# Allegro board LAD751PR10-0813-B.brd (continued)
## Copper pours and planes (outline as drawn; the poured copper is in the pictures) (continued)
P1 on IN1 (solid shape): 69.35,39.47 69.35,34.7 69.03,34.39 67.76,34.39 67.45,34.7 67.45,39.4 67.83,39.78 69.03,39.78
P1 on IN3 (solid shape): 69.6,39.59 69.6,34.64 69.22,34.26 67.95,34.26 67.57,34.64 67.57,39.53 67.83,39.78 69.41,39.78
P1 on IN4 (solid shape): 69.73,39.59 69.73,34.58 69.54,34.39 67.76,34.39 67.45,34.7 67.45,39.44 67.47,39.5 67.48,39.57 67.89,39.97 69.35,39.97
P2 on TOP (solid shape): outline of 89 points within 58.62,34.39 65.67,41.88
P2 on BOTTOM (solid shape): 64.14,42.13 64.14,40.25 66.07,38.32 66.07,34.11 65.83,33.87 61.56,33.87 61.51,33.81 61.16,33.81 60.97,34 60.97,38.01 60.35,38.62 59.13,38.62 59.13,41.94 58.36,41.94 58.36,38.62 57.03,38.62 56.78,38.87 56.78,43.09 57.1,43.4 62.87,43.4
P2 on IN1 (solid shape): 63.76,41.12 63.76,39.53 63.51,39.28 60.84,39.28 60.52,39.59 60.52,41.05 60.84,41.37 63.51,41.37
P2 on IN3 (solid shape): 63.89,41.12 63.89,39.59 63.64,39.34 60.71,39.34 60.52,39.53 60.52,41.24 60.65,41.37 63.64,41.37
P2 on IN4 (solid shape): 63.89,41.12 63.89,39.34 63.64,39.08 60.78,39.08 60.52,39.34 60.52,41.12 60.84,41.43 63.57,41.43
POK on BOTTOM (solid shape): 227.73,37.41 227.73,36.32 227.24,35.83 223.4,35.83 223.17,36.06 223.17,37.5 223.35,37.67 227.46,37.67
PQ703_S on TOP (solid shape): 82.24,32.04 82.24,29.12 82.05,28.92 80.91,28.92 80.65,29.18 78.62,29.18 78.56,29.24 78.56,29.69 78.3,29.94 77.22,29.94 76.72,30.45 76.72,32.1 77.16,32.54 81.73,32.54
PQ703_S on BOTTOM (solid shape): outline of 133 points within 72.34,21.56 80.97,32.16
PSID-1 on TOP (solid shape): 318.21,50.83 318.21,50.32 317.83,49.94 317.83,48.93 317.89,48.86 318.52,48.86 318.65,48.74 318.65,47.53 318.52,47.4 317.89,47.4 317.51,47.78 317.51,48.23 316.94,48.8 316.94,50.71 317.25,51.02 318.02,51.02
PSID-2 on TOP (solid shape): 316.56,51.47 316.56,49.75 315.1,48.29 313.83,48.29 313.57,48.55 313.57,48.99 314.46,49.88 314.46,50.77 314.65,50.96 315.48,50.96 315.67,51.15 315.67,51.47 315.92,51.72 316.3,51.72
PSID-3 on TOP (solid shape): 315.16,47.21 315.16,46.64 314.91,46.39 312.3,46.39 312.17,46.51 312.17,46.96 312.3,47.09 313.19,47.09 313.57,47.47 314.91,47.47
PWR_R# on TOP (solid shape): 211.15,170.21 211.15,168.5 211.01,168.36 210.66,168.36 210.48,168.54 210.48,169.98 209.87,170.59 209.87,170.9 210,171.03 210.33,171.03
PWR_VGA_CORE_BOOT2 on BOTTOM (solid shape): 246.98,36.22 246.98,35.21 246.9,35.13 246.9,35.09 245.79,33.98 245.48,33.98 245.41,34.05 245.41,34.82 245.48,34.89 245.53,34.92 245.6,34.92 245.69,34.83 245.82,34.83 245.83,34.82 246.26,34.92 246.26,35.37 246.25,35.38 246.25,35.41 246.07,35.58 246.01,35.58 246,35.6 246,35.75 245.97,35.79 245.97,36.25 246,36.29 246.91,36.29
PWR_VGA_CORE_BOOT2_1 on BOTTOM (solid shape): 248.22,37.71 248.22,37.04 248.15,36.96 246.02,36.96 245.95,37.03 245.95,37.61 246.14,37.8 248.13,37.8
PWR_VGA_CORE_PHASE1 on BOTTOM (solid shape): 264.49,34.13 264.49,25.94 264.36,25.81 263.19,25.81 262.67,26.33 262.07,26.33 262.01,26.39 262.01,30.96 261.19,31.78 260.55,31.78 260.33,32 260.33,34.42 260.49,34.58 264.04,34.58
PWR_VGA_CORE_PHASE2 on TOP (solid shape): 253.56,34.13 253.56,32.16 253.5,32.1 250.9,32.1 250.77,32.23 250.77,34.07 250.96,34.26 253.44,34.26
PWR_VGA_CORE_PHASE2 on BOTTOM (solid shape): 248.12,36.23 248.12,35.62 247.53,35.03 247.53,34.19 247.28,33.94 247.01,33.94 246.67,33.61 245.88,33.61 245.82,33.67 245.82,33.79 245.87,33.83 245.87,33.83 247.19,35.15 247.19,36.26 247.22,36.28 248.07,36.28
PWR_VGA_CORE_PHASE2 on BOTTOM (solid shape): 256.49,34.32 256.49,32.16 255.47,31.15 255.47,26.45 255.22,26.19 253.18,26.19 252.87,26.51 252.87,30.58 251.48,31.96 251.48,31.97 251.41,32.07 251.32,32.13 251.31,32.14 250.64,32.8 250.64,34.26 251.02,34.64 256.17,34.64
RING2 on TOP (solid shape): 28.92,22.23 28.92,20.86 29.05,20.73 29.54,20.73 29.68,20.59 29.68,19.99 29.54,19.84 28.25,19.84 28.18,19.91 28.18,21.41 28.18,21.43 28.01,21.6 28.01,22.26 28.07,22.31 28.84,22.31
RING2 on BOTTOM (solid shape): 26.65,31.34 26.73,31.3 26.75,31.21 26.74,31.07 26.78,30.94 26.79,30.92 27.02,30.76 27.29,30.81 27.5,30.81 27.69,30.75 27.89,30.81 29.06,30.81 29.12,30.75 29.12,30.65 29.04,30.56 27.26,30.56 27.25,30.55 27.13,30.55 27.08,30.5 26.32,30.5 26.24,30.58 26.07,30.58 25.91,30.75 25.91,31.33 25.92,31.34
RING2 on IN1 (solid shape): 28.33,21.11 28.33,20.93 28.52,20.73 29.28,20.73 29.41,20.61 29.41,20.03 29.22,19.84 27.63,19.84 27.31,20.16 27.31,21.3 28.14,21.3
RING2 on IN1 (solid shape): 26.85,30.84 26.85,30.24 26.58,29.98 24.59,29.98 24.4,30.16 24.4,31.3 24.55,31.45 24.62,31.45 24.67,31.46 26.22,31.46
RING2_R on TOP (solid shape): 28.06,21.36 28.06,19.42 28.33,19.15 28.33,17.56 28.01,17.24 27.31,17.24 27.16,17.4 27.16,17.74 27.16,17.81 27.16,17.88 27.16,18.67 26.9,18.92 26.9,21.2 27.11,21.41 28.01,21.41
RING2_R on TOP (solid shape): 22.16,19.98 22.16,19.39 21.38,18.62 20.02,18.62 19.48,18.08 18.78,18.08 18.6,18.26 18.6,18.28 18.23,18.65 17.47,18.65 17.24,18.88 17.24,19.7 17.43,19.89 18.61,19.89 19.14,19.37 19.41,19.37 19.73,19.68 20.74,19.68 21.14,20.09 22.06,20.09
RING2_R on BOTTOM (solid shape): 29.02,18.08 29.02,17.47 28.96,17.42 28.25,17.42 28.08,17.24 27.31,17.24 27.12,17.43 27.12,17.62 27.25,17.75 27.5,17.75 27.89,18.13 28.96,18.13
RING2_R on IN1 (solid shape): 17.87,19.83 17.87,18.65 17.29,18.08 16.47,18.08 16.35,18.19 16.35,19.63 16.62,19.89 17.8,19.89
RING2_R on IN1 (solid shape): 22.17,21.09 22.17,19.79 21.93,19.55 21.14,19.55 20.95,19.74 20.95,20.9 21.22,21.16 22.09,21.16
RING2_R on IN1 (solid shape): 28.28,18.6 28.28,17.61 27.89,17.22 27.36,17.22 27.14,17.44 27.14,17.68 27.13,17.96 26.93,18.15 26.91,18.17 26.91,18.5 27.52,19.11 27.77,19.11
RJ45_CT on TOP (solid shape): 263.5,165.37 263.5,164.64 263.27,164.42 248.15,164.42 247.82,164.75 247.82,165.47 247.94,165.59 263.28,165.59
RJ45_CT on BOTTOM (solid shape): 264.19,165.36 264.19,162.46 264.17,162.44 261.86,162.44 261.82,162.47 261.82,165.55 262.01,165.73 263.82,165.73
SLEEVE on BOTTOM (solid shape): 29.64,21.87 29.64,20.9 29.28,20.54 28.14,20.54 27.12,19.53 26.74,19.53 26.45,19.23 26.45,18.39 26.41,18.36 25.99,18.36 25.9,18.44 25.9,19.25 26.04,19.4 26.04,19.97 26.17,20.1 26.68,20.1 27.06,20.48 27.06,21.09 27.37,21.39 28.24,21.39 28.96,22.11 29.4,22.11
SLEEVE on IN1 (solid shape): 29.05,31.56 29.05,30.21 28.92,30.07 27.17,30.07 26.99,30.25 26.99,30.88 26.85,31.02 26.85,31.58 26.99,31.72 28.89,31.72
SLEEVE on IN1 (solid shape): 31.41,22.25 31.41,21.53 31.12,21.24 31.12,21.24 30.87,21.34 30.62,21.24 30.48,21.24 30.24,21.34 30,21.25 29.98,21.24 29.92,21.24 29.57,20.89 29.06,20.89 28.84,21.11 28.84,22.29 29.03,22.48 31.18,22.48
SLEEVE_R on TOP (solid shape): 21.18,18.17 21.18,16.61 20.28,15.7 19.72,15.7 19.12,16.3 17.61,16.3 17.45,16.47 17.45,17.57 17.5,17.62 18.14,17.62 18.35,17.53 18.55,17.62 19.36,17.62 20.07,18.33 21.01,18.33
SLEEVE_R on BOTTOM (solid shape): 31.32,21.05 31.32,20.59 30.26,19.54 30.25,19.54 30.1,19.39 29.32,19.39 29.02,19.08 27.57,19.08 27.31,18.83 27.31,18.51 27.19,18.38 26.68,18.38 26.66,18.41 26.66,19.19 26.74,19.27 27.06,19.27 27.65,19.87 28.26,19.87 28.27,19.86 28.46,19.81 28.64,19.87 28.89,19.87 29.18,19.82 29.41,20 29.41,20.01 29.48,20.08 29.48,20.43 29.92,20.86 29.92,21.11 30.04,21.24 31.12,21.24
SLEEVE_R on IN3 (solid shape): 17.95,17.24 17.95,16.1 17.6,15.74 16.63,15.74 16.54,15.83 16.54,17.02 16.82,17.3 17.89,17.3
SLEEVE_R on IN3 (solid shape): 21.04,18.98 21.04,17.86 20.93,17.75 20.1,17.75 19.87,17.98 19.87,19.16 19.9,19.18 20.84,19.18
SLEEVE_R on IN3 (solid shape): 31.33,21.02 31.33,20.31 30.49,19.46 30.48,19.46 29.72,18.7 28.71,18.7 28.71,19.59 28.84,19.72 29.08,19.72 29.17,19.81 29.19,19.82 29.34,19.91 29.44,20.07 29.44,20.08 29.65,20.29 29.65,21.09 29.84,21.28 31.07,21.28
SNB_1.0VS_VGAP on BOTTOM (solid shape): 248.19,45.56 248.19,44.74 248.26,44.67 248.95,44.67 249.02,44.61 249.02,43.78 248.95,43.72 248.26,43.72 247.75,44.23 247.75,44.6 247.75,44.72 247.49,44.97 247.49,45.63 247.56,45.69 248.07,45.69
SNUB_CHG on TOP (solid shape): 64.02,21.24 64.02,20.73 64.27,20.48 65.22,20.48 65.35,20.35 65.35,18.96 65.16,18.76 64.27,18.76 63.45,19.59 63.45,21.3 63.51,21.37 63.89,21.37
SPK_L+_CONN on TOP (solid shape): 30.67,17.12 30.67,16.8 30.61,16.74 30.34,16.74 30.21,16.61 30.21,16.08 30.12,16 29.54,16 29.47,16.06 29.47,16.54 29.47,16.54 29.47,16.98 29.59,17.11 29.59,17.12 29.66,17.18 30.61,17.18
SPK_L+_CONN on TOP (solid shape): 48.71,12.99 48.71,12.41 48.59,12.29 48.18,12.29 47.94,12.05 47.59,12.05 47.5,12.04 47.41,12.01 44.54,12.01 44.33,12.22 44.33,13.05 44.54,13.25 48.44,13.25
SPK_L+_CONN on BOTTOM (solid shape): 48.83,14.89 48.83,13.06 48.78,13.02 48.78,12.42 48.31,11.95 47.88,11.95 47.57,12.26 47.57,12.8 48.01,13.24 48.01,14.88 48.25,15.11 48.6,15.11
SPK_L+_CONN on BOTTOM (solid shape): 36.07,5.46 36.16,5.46 36.67,4.95 36.67,4.62 36.58,4.54 36.29,4.54 36.22,4.47 36.22,2.86 36.19,2.83 35.6,2.83 35.53,2.89 35.53,5.11 35.89,5.46 36.07,5.46
SPK_L+_CONN on IN1 (solid shape): 45.67,13.05 45.67,12.41 45.41,12.16 43.82,12.16 43.63,11.97 43.38,11.97 43.06,12.29 43.06,12.8 43.57,13.3 45.41,13.3
SPK_L+_CONN on IN1 (solid shape): 36.73,6.09 36.73,6.06 36.71,6.04 36.69,6.02 36.71,6 36.71,5.68 36.65,5.62 36.54,5.62 36.41,5.49 36.41,5.24 36.59,5.06 36.65,4.99 36.71,4.94 36.71,4.53 36.66,4.47 35.81,4.47 35.42,4.86 35.42,6.21 35.81,6.59 36.23,6.59
SPK_L+_CONN on IN3 (solid shape): 30.81,17.07 30.81,16.6 31.06,16.35 31.06,15.59 30.81,15.34 30.11,15.34 29.57,15.88 29.57,17.11 29.77,17.32 30.55,17.32
SPK_L+_CONN on IN3 (solid shape): 37.28,6.7 37.28,6.06 37.03,5.81 36.71,5.81 36.46,5.56 36.46,5.11 36.71,4.86 36.71,4.6 36.52,4.41 35.63,4.41 35.44,4.6 35.44,6.06 36.27,6.89 37.09,6.89
SPK_L-_CONN on TOP (solid shape): 32.93,17.06 32.93,16.88 32.77,16.72 32.77,16.05 32.73,16.01 32.1,16.01 32.06,16.05 32.06,16.75 31.93,16.88 31.93,17.07 32.08,17.22 32.77,17.22
SPK_L-_CONN on TOP (solid shape): 46.24,11.1 47.28,11.1 47.48,10.9 48.57,10.9 48.75,10.73 48.75,10.02 48.62,9.89 46.03,9.89 45.28,10.64 45.28,11.53 45.41,11.65 45.68,11.65
SPK_L-_CONN on BOTTOM (solid shape): 39.75,3.98 39.75,3.14 39.56,2.95 39.19,2.95 39.06,3.08 37.45,3.08 37.4,3.13 37.4,4.02 37.48,4.1 38.42,4.1 38.42,4.1 39.63,4.1
SPK_L-_CONN on BOTTOM (solid shape): 50.08,14.91 50.08,10.81 49.19,9.92 47.65,9.92 47.51,10.07 47.51,10.93 47.63,11.06 48.7,11.06 49.13,11.48 49.13,13.05 49.28,13.21 49.28,14.93 49.47,15.12 49.87,15.12
SPK_L-_CONN on IN1 (solid shape): 39.58,5.36 39.58,3.2 39.32,2.95 39.07,2.95 39,3.02 39,3.33 38.37,3.96 38.37,5.05 38.74,5.42 39.51,5.42
SPK_L-_CONN on IN1 (solid shape): 45.87,11.53 45.87,10.4 45.72,10.25 43.64,10.25 43.51,10.38 43.51,11.08 44.05,11.62 45.78,11.62
SPK_L-_CONN on IN3 (solid shape): 32.96,17.12 32.96,15.28 32.77,15.09 32.07,15.09 31.88,15.28 31.88,16.54 31.95,16.61 31.95,17.12 32.08,17.25 32.83,17.25
SPK_L-_CONN on IN3 (solid shape): 39.59,4.59 39.59,3.06 39.44,2.92 38.97,2.92 38.24,3.65 38.24,4.79 38.36,4.92 39.25,4.92
SPK_R+_CONN on TOP (solid shape): 27.5,11.6 27.94,11.6 28.07,11.47 28.07,10.96 28.01,10.9 26.87,10.9 26.74,11.03 26.74,11.91 26.81,11.97 27.12,11.97
SPK_R+_CONN on TOP (solid shape): 48.75,9.06 48.75,8.34 48.61,8.21 47.51,8.21 47.28,7.98 45.69,7.98 45.19,7.48 44.75,7.48 44.34,7.89 44.34,8.15 45.38,9.19 48.62,9.19
SPK_R+_CONN on TOP (solid shape): 30.55,4.79 30.55,3.21 30.23,2.89 27,2.89 26.74,3.14 26.74,4.03 26.87,4.16 27.95,4.16 28.01,4.1 28.01,3.81 28.2,3.62 29.38,3.62 29.85,4.1 29.85,4.73 29.98,4.86 30.49,4.86
SPK_R+_CONN on BOTTOM (solid shape): 51.32,14.91 51.32,13.08 51.48,12.92 51.48,9.98 49.69,8.2 47.76,8.2 47.57,8.39 47.57,9.35 47.7,9.47 49.4,9.47 50.55,10.63 50.52,10.66 50.52,14.9 50.74,15.13 51.1,15.13
SPK_R+_CONN on IN3 (solid shape): 28.2,4.54 28.2,4.29 28.01,4.1 28.01,3.59 27.82,3.4 26.87,3.4 26.74,3.52 26.74,4.22 27.63,5.11
SPK_R+_CONN on IN3 (solid shape): 27.63,11.53 28.26,11.53 28.51,11.28 28.51,10.39 28.39,10.26 27.76,10.26 27.51,10.51 27.5,10.51 27.5,10.64 27.38,10.76 26.93,10.76 26.74,10.95 26.74,11.91 26.81,11.97 27.19,11.97
SPK_R+_CONN on IN4 (solid shape): 45.79,8.54 45.79,7.84 45.49,7.54 43.62,7.54 43.57,7.59 43.57,8.48 43.71,8.62 45.72,8.62
SPK_R+_CONN on IN4 (solid shape): 28.14,4.48 28.14,4.29 27.94,4.09 27.94,3.68 27.72,3.46 26.87,3.46 26.8,3.53 26.81,3.67 26.81,4.35 27.44,4.99 27.63,4.99
SPK_R-_CONN on TOP (solid shape): 28.04,14.23 28.04,13.72 27.82,13.49 26.87,13.49 26.74,13.62 26.74,14.38 27,14.64 27.64,14.64
SPK_R-_CONN on TOP (solid shape): 47.6,6.78 48.62,6.78 48.75,6.65 48.75,6.02 48.62,5.89 45.38,5.89 45.19,6.08 45.19,6.9 45.38,7.09 47.28,7.09
SPK_R-_CONN on BOTTOM (solid shape): 31.13,4.15 31.13,2.18 30.13,1.18 28.77,1.18 28.65,1.3 28.65,1.68 28.9,1.94 29.6,1.94 30.23,2.57 30.23,4.14 30.3,4.21 31.08,4.21
SPK_R-_CONN on BOTTOM (solid shape): 52.59,14.9 52.59,13.43 52.84,13.18 52.84,9.04 50.74,6.93 48.97,6.93 48.78,6.74 48.78,6.26 48.59,6.07 47.67,6.07 47.54,6.2 47.54,7.68 47.86,8 50.24,8 51.82,9.58 51.82,13.14 51.77,13.19 51.77,14.94 51.96,15.13 52.36,15.13
SPK_R-_CONN on IN3 (solid shape): 28.52,14.19 28.52,13.3 28.39,13.18 27.57,13.18 27.25,13.49 26.93,13.49 26.74,13.68 26.74,14.51 26.93,14.7 28.01,14.7
SPK_R-_CONN on IN3 (solid shape): 30.68,1.56 30.36,1.23 29.61,1.23 29.6,1.23 28.78,1.23 28.58,1.43 28.58,1.81 28.71,1.94 29.47,1.94 29.66,2.13 29.66,3.65 30.68,3.65
SPK_R-_CONN on IN4 (solid shape): 31.19,1.81 30.55,1.18 28.84,1.18 28.71,1.3 28.71,1.81 28.84,1.94 29.73,1.94 29.85,2.06 29.85,2.45 30.23,2.83 31.19,2.83
SPK_R-_CONN on IN4 (solid shape): 45.98,6.95 45.98,5.81 45.86,5.68 44.46,5.68 44.2,5.94 44.2,6.7 44.97,6.7 45.41,7.14 45.79,7.14
SW_1.2V on TOP (solid shape): outline of 330 points within 86.43,36.54 98.69,41.75
SW_1.2V on BOTTOM (solid shape): 91.59,43.24 91.59,43.12 90.8,42.33 90.55,42.08 90.55,41.87 90.18,41.5 89.3,41.5 89.23,41.57 89.23,42.41 89.31,42.5 90.1,42.5 90.69,43.08 90.69,43.24 90.75,43.3 91.53,43.3
SW_1.2V on BOTTOM (solid shape): outline of 83 points within 87.07,33.21 92.32,40.23
SW_1.2V on IN4 (solid shape): 90.93,42.84 90.93,42.52 90.26,41.86 90.26,41.45 89.86,41.05 89.2,41.05 89.2,41.91 89.86,42.57 90.17,42.57 90.56,42.96 90.81,42.96
SW_1.2V on IN4 (solid shape): 90.24,40.35 90.24,39.97 90.43,39.78 90.43,39.53 90.63,39.33 90.63,39.15 90.43,38.96 90.12,38.96 89.23,39.85 89.23,40.42 90.18,40.42
SW_+1VALWP on TOP (solid shape): 254.64,21.83 254.64,20.16 254.6,20.12 253.44,20.12 253.36,20.03 253.03,20.03 252.9,19.91 252.9,19.82 252.87,19.78 252.87,18.99 252.88,18.98 252.85,18.96 252.84,18.95 252.65,18.66 252.9,18.41 253.08,18.37 253.25,18.45 255.6,18.45 255.85,18.19 255.85,15.91 255.53,15.59 252.93,15.59 251.47,17.05 247.51,17.05 246.81,17.75 246.77,17.75 246.64,17.88 245.82,17.88 245.75,17.94 245.75,18.13 245.82,18.19 247.07,18.19 247.18,18.15 247.29,18.14 247.41,18.15 247.51,18.19 247.6,18.19 247.91,17.88 250.66,17.88 251.33,18.54 251.33,21.2 252.11,21.98 254.49,21.98
SW_+1VALWP on BOTTOM (solid shape): outline of 92 points within 251.34,17.39 258.93,21.91
TBT_SVR_IND on TOP (solid shape): 175.01,169.45 175.4,169.45 175.81,169.04 176.41,169.04 176.47,168.97 176.47,168.84 176.41,168.78 176.28,168.78 176.09,168.59 176.09,168.46 176.04,168.41 175.6,168.41 175.59,168.42 175.53,168.45 175.47,168.46 175.17,168.46 174.81,168.1 169.62,168.1 169.19,168.54 169.19,169.75 169.72,170.28 174.19,170.28
TBT_SVR_IND on BOTTOM (solid shape): 175.19,169.53 175.19,168.23 174.98,168.02 169.45,168.02 169.07,168.4 169.07,169.56 169.36,169.84 174.88,169.84
UG_3V on TOP (solid shape): 53.79,29.5 53.79,28.99 53.48,28.67 52.52,28.67 52.4,28.8 52.4,29.31 52.46,29.37 52.97,29.37 53.29,29.69 53.6,29.69
UG_3V on BOTTOM (solid shape): 56.65,44.17 56.65,43.92 56.46,43.73 56.01,43.73 55,44.74 55,44.93 55.06,45 55.82,45
UG_3V on IN4 (solid shape): 57.98,42.96 57.98,42.71 57.54,42.26 57.28,42.26 56.33,43.22 56.33,43.34 55.63,44.04 55.63,44.49 55.82,44.68 56.27,44.68
UG_3V on IN4 (solid shape): 53.41,30.45 53.29,30.32 53.29,30.07 53.79,29.56 53.79,29.24 53.29,28.73 52.84,28.73 52.14,29.43 52.14,30.51 52.4,30.77 53.41,30.77
UG_5V on TOP (solid shape): 47.32,37.19 47.32,36.23 47.13,36.04 46.49,36.04 46.3,36.23 46.3,37.17 46.42,37.29 47.22,37.29
UG_5V on BOTTOM (solid shape): 52.78,44.91 52.78,44.84 52.17,44.23 52.17,43.17 51.95,42.95 51.27,42.95 51.15,43.07 51.15,43.91 51.52,44.28 51.52,44.75 51.75,44.98 52.7,44.98
UG_5V on IN4 (solid shape): 47.13,37.18 47.32,36.99 47.32,36.23 47.13,36.04 46.3,36.04 46.11,36.23 46.11,38.07 47.13,38.07
UG_5V on IN4 (solid shape): 52.01,44.55 52.01,43.47 51.19,42.65 50.81,42.65 50.36,43.09 50.36,43.53 51.51,44.68 51.89,44.68
UG_+1VALWP on TOP (solid shape): 254.64,19.83 254.64,18.89 254.35,18.6 253.44,18.6 252.99,19.04 252.99,19.73 253.12,19.86 253.5,19.86 253.63,19.98 254.49,19.98
UG_+1VALWP on TOP (solid shape): 247.54,19.32 247.54,18.37 247.49,18.32 247.47,18.32 247.44,18.3 247.37,18.27 247.29,18.26 247.21,18.27 247.14,18.3 247.11,18.32 246.58,18.32 246.55,18.35 245.89,18.35 245.79,18.45 245.79,18.56 245.88,18.65 246.54,18.65 246.59,18.7 246.63,18.7 246.83,18.9 246.83,19.35 246.91,19.42 247.44,19.42
UG_+1VALWP on IN1 (solid shape): 248.46,19.09 248.46,18.38 248.13,18.05 247.3,18.05 247.06,18.29 247.06,19.22 247.25,19.41 248.14,19.41
UG_+1VALWP on IN1 (solid shape): 253.7,19.6 253.7,18.19 253.34,17.82 253.11,17.82 252.51,18.42 252.51,18.65 252.66,18.89 252.58,19.17 252.56,19.23 252.58,19.3 252.64,19.41 252.66,19.53 252.66,19.55 252.94,19.82 253.48,19.82
N3691692 on TOP (solid shape): 248.77,21.15 248.77,18.61 248.74,18.57 247.85,18.57 247.76,18.66 247.76,19.43 247.56,19.63 247.56,21.21 247.63,21.27 248.64,21.27
N3691782 on BOTTOM (solid shape): 258.89,19.07 258.89,17.95 258.78,17.83 257.93,17.83 257.83,17.73 257.83,17.01 257.77,16.95 257.16,16.95 257.11,17 257.11,19.04 257.26,19.19 258.78,19.19
N4123408 on BOTTOM (solid shape): 59,45.94 59,44.16 58.87,44.04 58.37,44.04 58.05,44.36 58.05,45.94 58.17,46.07 58.87,46.07
N4123550 on TOP (solid shape): 44.27,31.21 44.27,30.32 44.4,30.19 45.28,30.19 45.41,30.07 45.41,29.12 45.28,28.99 43.51,28.99 43.13,29.37 43.13,31.21 43.19,31.27 44.21,31.27
N4123582 on TOP (solid shape): 44.52,32.61 44.52,31.62 44.41,31.5 42.07,31.5 41.8,31.77 41.8,32.87 41.86,32.93 44.2,32.93
N4124695 on BOTTOM (solid shape): 49.67,45.69 49.67,44.23 49.54,44.1 48.9,44.1 48.78,44.23 48.78,45.75 48.97,45.94 49.41,45.94
N16758539 on TOP (solid shape): 303.55,52.5 303.55,52.38 303.55,52.37 303.55,51.04 303.56,51.02 303.67,51.02 303.79,50.9 303.79,49.05 303.86,48.99 304.95,48.99 305.09,48.86 305.09,48.19 304.94,48.04 302.99,48.04 302.89,48.15 302.89,48.73 303.27,49.12 303.27,51.01 303.33,51.07 303.33,52.51 303.38,52.56 303.49,52.56
N16760382 on TOP (solid shape): 300.43,57.44 300.43,56.61 302.4,54.64 302.4,54.39 302.33,54.32 301.44,54.32 301.32,54.45 301.32,54.71 299.28,56.74 298.71,56.74 298.44,57.01 298.44,57.67 298.52,57.75 300.11,57.75
N16788038 on TOP (solid shape): 69.6,40.74 69.6,39.91 69.51,39.82 68.14,39.82 67.76,39.43 67.76,38.85 67.7,38.79 67.66,38.72 67.65,38.71 67.52,38.58 66.49,38.58 66.43,38.64 66.43,39.59 66.83,39.99 66.83,40.79 66.96,40.93 69.41,40.93
N17230179 on TOP (solid shape): 299.12,51.95 299.12,50.04 298.96,49.88 298.34,49.88 298.19,50.03 298.19,51.62 298.18,51.63 298.18,52.11 298.2,52.13 298.93,52.13
N17235867 on TOP (solid shape): 307.56,57.19 307.5,57.13 307.01,57.13 306.85,56.98 306.85,56.24 306.68,56.07 306.68,55.54 306.17,55.02 305.63,55.02 305.44,54.83 305.44,54.39 305.38,54.32 304.62,54.32 304.55,54.39 304.55,54.71 306.37,56.52 306.37,57.66 306.5,57.79 307.56,57.79
N17244731 on TOP (solid shape): 317.25,48.1 317.25,47.34 317.57,47.02 318.91,47.02 319.86,47.97 320.3,47.97 320.62,47.66 320.62,46.64 320.3,46.32 316.43,46.32 315.6,47.15 315.6,48.04 315.98,48.42 316.94,48.42
N18456772 on TOP (solid shape): 60.78,24.42 60.78,24.16 59.94,23.32 59.1,23.32 59.02,23.4 59.02,23.62 59.37,23.97 59.75,23.97 60.33,24.55 60.65,24.55
N18456859 on TOP (solid shape): 63.13,23.34 63.13,21.24 63,21.11 62.43,21.11 62.37,21.18 62.37,22.13 62.56,22.32 62.56,22.77 62.37,22.96 62.37,23.53 62.43,23.59 62.87,23.59
N19529526 on TOP (solid shape): 40.65,8.88 40.65,8.22 39.93,7.49 37.21,7.49 37.15,7.56 37.15,7.68 37.21,7.75 38.11,7.75 38.77,8.41 39.25,8.41 39.44,8.6 39.44,8.92 39.59,9.07 40.46,9.07
N19529526 on BOTTOM (solid shape): 41.06,8.56 41.06,6.86 40.65,6.45 40.01,7.08 40.01,7.72 39.51,8.22 39.51,8.99 39.62,9.1 40.52,9.1
N19529527 on TOP (solid shape): 34.34,6.65 34.34,5.84 34.42,5.76 34.42,4.99 34.55,4.86 34.6,4.8 34.66,4.75 34.8,4.61 35.06,4.61 35.12,4.55 35.12,3.66 35.05,3.6 34.33,3.6 34.25,3.68 34.25,4.71 34.14,4.82 34.14,6.65 34.19,6.7 34.29,6.7
N19529528 on TOP (solid shape): 33.95,6.65 33.95,5.79 33.99,5.75 33.99,4.78 34.1,4.66 34.1,3.78 34.04,3.72 33.47,3.72 33.47,4.89 33.72,5.14 33.72,5.8 33.73,5.81 33.73,6.64 33.8,6.7 33.9,6.7
N19529529 on TOP (solid shape): 30.95,7.68 30.95,7.56 30.88,7.49 30.06,7.49 29.56,6.99 29.56,6.66 29.41,6.51 28.77,6.51 28.65,6.64 28.65,7.46 28.72,7.53 29.21,7.53 29.42,7.75 30.88,7.75
N19616930 on TOP (solid shape): 226.85,116.67 226.85,114.92 226.84,114.91 226.81,114.78 226.84,114.65 226.85,114.64 226.85,113.43 226.84,113.42 226.84,111.56 226.88,111.51 226.85,111.48 226.78,111.11 227.11,110.93 227.19,110.91 227.22,110.83 227.22,110.34 227.05,110.17 226.15,110.17 225.97,110.35 225.97,111.14 225.97,111.15 225.99,111.25 225.97,111.35 225.97,111.36 225.97,111.84 225.97,111.85 225.99,111.95 225.97,112.05 225.97,112.06 225.97,113.81 226.06,113.9 226.06,114.87 225.76,115.16 224.57,115.16 223.85,115.88 223.85,116.68 223.94,116.77 226.75,116.77
N20474318 on TOP (solid shape): 31.25,2.7 31.25,1.87 31.31,1.81 31.31,1.3 31.19,1.18 30.68,1.18 30.62,1.24 30.62,2.7 30.68,2.76 31.19,2.76
N20474322 on TOP (solid shape): 35.66,3.21 35.66,2.36 36.08,1.94 36.08,1.37 36.01,1.3 35.51,1.3 35.44,1.37 35.44,1.91 34.97,2.38 34.97,3.23 35.02,3.28 35.58,3.28
N20474324 on BOTTOM (solid shape): 40.6,5.21 40.6,5.06 40.21,4.67 39.75,4.67 39.43,4.35 38.9,4.35 38.86,4.39 38.86,4.94 38.92,5 39.57,5 40.18,5.61 40.2,5.61
N21000719 on BOTTOM (solid shape): outline of 90 points within 170.98,158.09 172.73,160.77
N24654525 on TOP (solid shape): 227.82,42.57 227.94,42.57 228.13,42.39 228.95,42.39 229,42.34 229,41.79 228.93,41.71 228.32,41.71 228.04,41.43 228.04,36.86 227.91,36.74 225.92,36.74 225.75,36.9 225.75,37.32 226.3,37.32 226.3,37.88 225.75,37.88 225.75,38.12 226.3,38.12 226.3,38.69 225.76,38.69 225.76,40.98 226.55,40.98 226.55,40.92 226.57,40.87 226.59,40.82 226.61,40.78 226.65,40.73 226.68,40.7 226.73,40.67 226.78,40.64 226.83,40.63 226.88,40.62 226.93,40.62 226.99,40.63 227.04,40.64 227.09,40.67 227.13,40.7 227.17,40.73 227.2,40.78 227.23,40.82 227.25,40.87 227.26,40.92 227.26,40.98 227.26,41.03 227.25,41.08 227.23,41.13 227.2,41.18 227.17,41.22 227.13,41.26 227.09,41.29 227.04,41.31 226.99,41.32 226.93,41.33 226.88,41.33 226.83,41.32 226.78,41.31 226.73,41.29 226.68,41.26 226.65,41.22 226.61,41.18 226.59,41.13 226.57,41.08 226.55,41.03 226.55,40.98 225.76,40.98 225.76,41.51 226.83,42.58 227.82,42.58
N26590633 on BOTTOM (solid shape): 23.44,53.75 23.44,52.57 23.35,52.48 23.23,52.34 23.19,52.17 23.19,51.75 23.28,51.66 23.28,50.86 23,50.58 23,48.24 22.68,47.91 21.38,47.91 21.24,48.05 21.24,51.13 20.92,51.44 20.92,51.45 20.59,51.7 20.25,51.47 20.24,51.44 19.98,51.44 19.95,51.4 19,51.4 18.93,51.47 18.93,52.23 19,52.29 19,53.12 19.12,53.25 20.07,53.25 20.84,54.01 20.84,54.07 20.9,54.13 23.06,54.13
N29425467 on BOTTOM (solid shape): 174.46,141.73 174.46,140.55 174.59,140.43 178.33,140.43 178.53,140.23 178.53,138.56 178.77,138.32 178.77,136.18 178.74,136.15 173.78,136.15 173.5,136.44 173.5,141.76 173.56,141.82 174.37,141.82
N29425497 on BOTTOM (solid shape): 166.12,141.67 166.12,140.53 166.24,140.4 169.99,140.4 170.12,140.27 170.12,137.97 170.83,137.26 172.63,137.26 172.79,137.09 172.79,133.62 172.44,133.27 170.32,133.27 169.44,134.14 169.44,135.36 167.77,137.03 167.76,137.03 165.15,139.64 165.15,141.73 165.28,141.86 165.93,141.86
N29425633 on BOTTOM (solid shape): 157.79,141.72 157.79,140.58 157.91,140.45 161.66,140.45 161.79,140.32 161.79,138.73 161.13,138.07 159.99,138.07 159.05,137.13 159.05,134.27 158.52,133.74 155.01,133.74 154.92,133.83 154.92,134.47 154.95,134.59 154.92,134.72 154.92,135.1 154.95,135.23 154.92,135.35 154.92,137.97 155.57,138.61 155.58,138.61 156.82,139.85 156.82,141.71 156.96,141.85 157.65,141.85
N29435109 on BOTTOM (solid shape): 186.06,137.7 186.06,134.6 185.43,133.97 181.63,133.97 181.53,134.07 181.53,138.44 182.38,139.29 184.47,139.29
N29435333 on BOTTOM (solid shape): 150.1,144.99 150.1,143.84 150.23,143.72 153.98,143.72 154.1,143.59 154.1,139.62 153.93,139.44 148.98,139.44 148.93,139.49 148.93,144.84 149.26,145.18 149.91,145.18
N29436554 on BOTTOM (solid shape): 141.77,144.96 141.77,143.82 141.9,143.69 145.64,143.69 145.77,143.56 145.77,139.59 145.6,139.42 141.09,139.42 140.81,139.7 140.81,140.88 141.06,140.88 141.07,140.82 141.08,140.77 141.1,140.72 141.12,140.67 141.16,140.63 141.2,140.6 141.24,140.57 141.29,140.54 141.34,140.53 141.39,140.52 141.45,140.52 141.5,140.53 141.55,140.54 141.6,140.57 141.64,140.6 141.68,140.63 141.71,140.67 141.74,140.72 141.76,140.77 141.77,140.82 141.78,140.88 141.77,140.93 141.76,140.98 141.74,141.03 141.71,141.08 141.68,141.12 141.64,141.15 141.6,141.18 141.55,141.21 141.5,141.22 141.45,141.23 141.39,141.23 141.34,141.22 141.29,141.21 141.24,141.18 141.2,141.15 141.16,141.12 141.12,141.08 141.1,141.03 141.08,140.98 141.07,140.93 141.06,140.88 140.81,140.88 140.81,145.02 140.93,145.15 141.58,145.15
N30964087 on BOTTOM (solid shape): 291.23,87.62 291.23,86.11 290.99,85.87 290.76,85.87 290.6,86.04 290.6,87.69 290.61,87.7 291.16,87.7
N31204217 on TOP (solid shape): 309.4,60.96 309.4,60.42 309.21,60.24 308.22,60.24 307.97,60.33 307.73,60.24 307.58,60.24 307.35,60.33 307.12,60.26 307.01,60.37 307.01,60.96 307.03,60.98 309.37,60.98
N31227804 on BOTTOM (solid shape): 289.35,78.53 289.35,78.02 289.21,77.88 287.82,77.88 287.65,78.05 287.65,78.67 287.69,78.71 289.18,78.71
N31425872 on BOTTOM (solid shape): 160.9,146.61 160.9,145.97 160.25,145.32 160.25,144.6 160.15,144.5 160.01,144.5 159.92,144.59 159.92,146.6 159.99,146.67 160.84,146.67
N31425874 on BOTTOM (solid shape): 162.14,148.04 162.17,148 162.17,147.44 162.12,147.39 159.97,147.39 159.92,147.44 159.92,147.99 159.97,148.04 162.1,148.04
N31425876 on BOTTOM (solid shape): 162.19,146.58 162.19,145.9 161.98,145.69 161.51,145.69 161.23,145.41 161.23,144.58 161.17,144.51 160.98,144.51 160.91,144.58 160.91,145.61 161.23,145.93 161.23,146.59 161.28,146.64 162.12,146.64
N31433757 on BOTTOM (solid shape): 170.47,147.99 170.5,147.95 170.5,147.39 170.45,147.34 168.31,147.34 168.25,147.39 168.25,147.94 168.31,147.99 170.43,147.99
N31433760 on BOTTOM (solid shape): 169.23,146.55 169.23,145.92 168.58,145.26 168.58,144.63 168.45,144.5 168.33,144.5 168.26,144.57 168.26,146.56 168.32,146.62 169.17,146.62
N31433761 on BOTTOM (solid shape): 170.52,146.53 170.52,145.85 170.31,145.64 169.84,145.64 169.56,145.36 169.56,144.53 169.5,144.46 169.31,144.46 169.24,144.53 169.24,145.56 169.56,145.87 169.56,146.54 169.62,146.59 170.45,146.59
N31436196 on BOTTOM (solid shape): 178.81,148.01 178.85,147.98 178.85,147.42 178.8,147.37 176.65,147.37 176.6,147.42 176.6,147.96 176.65,148.02 178.78,148.02
N31436215 on BOTTOM (solid shape): 177.58,146.58 177.58,145.94 176.91,145.28 176.91,144.56 176.82,144.47 176.69,144.47 176.59,144.57 176.59,146.57 176.66,146.64 177.51,146.64
N31436218 on BOTTOM (solid shape): 178.86,146.55 178.86,145.87 178.66,145.67 178.19,145.67 177.9,145.38 177.9,144.55 177.84,144.49 177.65,144.49 177.59,144.55 177.59,145.58 177.9,145.9 177.9,146.56 177.96,146.62 178.8,146.62
N31439632 on BOTTOM (solid shape): 146.12,151.28 146.16,151.24 146.16,150.68 146.11,150.63 143.96,150.63 143.91,150.68 143.91,151.23 143.96,151.28 146.09,151.28
N31439653 on BOTTOM (solid shape): 144.89,149.84 144.89,149.21 144.23,148.55 144.23,147.92 144.11,147.79 143.98,147.79 143.92,147.86 143.92,149.85 143.97,149.91 144.82,149.91
N31439658 on BOTTOM (solid shape): 146.17,149.82 146.17,149.14 145.97,148.93 145.5,148.93 145.21,148.65 145.21,147.81 145.15,147.75 144.96,147.75 144.9,147.81 144.9,148.85 145.21,149.16 145.21,149.82 145.27,149.88 146.11,149.88
N31452286 on BOTTOM (solid shape): 153.22,149.87 153.22,149.23 152.55,148.56 152.55,147.85 152.46,147.76 152.33,147.76 152.25,147.85 152.24,147.92 152.24,148.5 152.25,148.54 152.25,149.27 152.24,149.28 152.24,149.87 152.3,149.93 153.15,149.93
N31452288 on BOTTOM (solid shape): 154.45,151.3 154.49,151.27 154.49,150.71 154.44,150.66 152.29,150.66 152.24,150.71 152.24,151.25 152.29,151.3 154.42,151.3
N31452290 on BOTTOM (solid shape): 154.5,149.84 154.5,149.16 154.3,148.96 153.83,148.96 153.55,148.67 153.55,147.84 153.48,147.78 153.29,147.78 153.23,147.84 153.23,148.87 153.55,149.19 153.55,149.85 153.6,149.91 154.44,149.91
N31470989 on TOP (solid shape): 80.84,28.42 82.05,28.42 82.24,28.23 82.24,27.15 82.11,27.02 79.57,27.02 79.45,27.15 79.45,28.67 79.51,28.73 80.53,28.73
N31483118 on BOTTOM (solid shape): 239.05,34.53 239.05,34.04 238.58,33.57 238.58,33.5 238.57,33.49 238.53,33.31 238.57,33.13 238.58,33.11 238.58,33.08 238.68,32.98 238.72,32.98 238.73,32.97 238.91,32.92 239.09,32.97 239.1,32.98 239.23,32.98 239.35,32.85 239.35,32.42 239.24,32.3 238.38,32.3 238.18,32.49 238.18,32.81 238.12,32.88 238.12,32.89 237.99,33.03 237.99,33.98 238.17,34.16 238.18,34.17 238.34,34.29 238.41,34.48 238.41,34.5 238.53,34.61 238.96,34.61
N31487055 on BOTTOM (solid shape): 232.99,39.71 232.99,37.31 233,37.29 233,35.15 232.55,34.69 231.19,34.69 230.88,35 230.88,37.86 231.02,38.14 230.88,38.43 230.88,39.35 230.72,39.52 230.72,40.98 230.83,41.09 231.61,41.09
N31487107 on BOTTOM (solid shape): 234.48,42.89 234.48,42.63 234.49,42.62 234.49,40.62 234.37,40.51 233.71,40.51 233.54,40.68 233.54,42.86 233.7,43.02 234.35,43.02
N31487111 on BOTTOM (solid shape): 233.07,41.5 233.07,40.63 233,40.57 232.34,40.57 231.68,41.23 230.82,41.23 230.7,41.35 230.7,41.45 231,41.74 232.83,41.74
N31494164 on BOTTOM (solid shape): 185.68,146.45 185.68,145.87 185.62,145.81 183.48,145.81 183.42,145.87 183.42,146.46 183.49,146.53 185.6,146.53
N31494196 on BOTTOM (solid shape): 184.45,145.09 184.45,144.41 184.09,144.05 184.09,142.97 184.03,142.91 183.84,142.91 183.77,142.97 183.77,143.95 183.49,144.24 183.49,145.12 183.57,145.2 184.35,145.2
N31494209 on BOTTOM (solid shape): 185.64,145.07 185.66,145.02 185.68,144.97 185.68,144.05 184.54,142.91 184.35,142.91 184.28,142.97 184.28,143.88 184.67,144.27 184.67,145.08 184.82,145.23 185.49,145.23
N31787119 on TOP (solid shape): 256.68,154.56 256.68,153.99 256.17,153.48 254.83,153.48 254.77,153.54 254.77,154.11 254.83,154.18 255.28,154.18 255.72,154.62 256.61,154.62
N32274706 on TOP (solid shape): 284.1,49.96 284.88,49.96 285,49.84 285,48.55 284.81,48.36 283.66,48.36 280.42,51.59 278.71,51.59 278.52,51.78 278.52,52.61 278.71,52.8 281.25,52.8
N32274706 on TOP (solid shape): 297.62,51.71 297.93,51.71 298.06,51.57 298.06,49.92 298.36,49.63 299.47,49.63 299.54,49.55 299.54,47.54 299.28,47.28 298.52,47.28 298.33,47.47 298.33,48.86 297.2,49.99 297.2,51.51 297.4,51.71 297.62,51.71
N32274706 on BOTTOM (solid shape): outline of 125 points within 277.38,39.07 285.06,54.9
N32274716 on TOP (solid shape): 297.82,54.17 297.82,53.58 298.12,53.28 299,53.28 299.1,53.18 299.1,52.56 299.01,52.48 298.36,52.48 297.91,52.03 297.24,52.03 296.74,52.53 296.74,54.18 296.81,54.25 297.75,54.25
N32274716 on BOTTOM (solid shape): 287.56,44.37 287.56,42.85 287.36,42.65 286.87,42.65 286.7,42.82 286.7,44.33 286.86,44.5 287.44,44.5
N32274716 on BOTTOM (solid shape): 287.96,49.91 287.96,48.82 287.56,48.41 286.81,48.41 286.58,48.65 286.58,49.91 286.72,50.05 287.82,50.05
N32274716 on IN1 (solid shape): 289.44,49.94 289.44,48.97 289.4,48.93 286.89,48.93 286.83,48.99 286.83,49.88 286.94,49.99 289.39,49.99
N32274716 on IN1 (solid shape): 297.81,54.13 297.81,52.77 297.01,51.97 296.83,51.97 296.3,52.49 296.3,52.7 296.78,53.17 296.78,54.15 296.92,54.29 297.65,54.29
N32274716 on IN2 (solid shape): 287.28,45.41 287.28,44.67 287.56,44.4 287.56,43.65 287.38,43.47 287.06,43.47 286.27,44.26 286.27,45.45 286.31,45.49 287.2,45.49
N32274716 on IN2 (solid shape): 287.94,49.88 287.94,49.34 287.37,48.78 287.37,48.78 287.29,48.7 287.29,48.42 287.21,48.34 286.34,48.34 286.27,48.42 286.27,49.3 287.01,50.05 287.77,50.05
N32295361 on TOP (solid shape): 290.53,50.9 290.53,50.07 290.28,49.82 288.63,49.82 288.5,49.94 288.5,51.09 288.64,51.23 290.2,51.23
N32295361 on TOP (solid shape): 308.81,48.93 308.81,48.42 307.83,47.44 305.28,47.44 305.13,47.59 305.13,47.97 305.16,48.01 305.21,48.01 305.21,48.05 305.25,48.1 306.64,48.1 306.88,48.34 306.88,48.92 306.95,48.99 308.75,48.99
N32295361 on BOTTOM (solid shape): outline of 89 points within 288.11,39.09 293.99,55.15
N32295361 on IN6 (solid shape): 295.28,43.85 295.28,43.09 295.16,42.96 293.06,42.96 292.87,43.15 292.87,43.78 293,43.91 295.22,43.91
N32295361 on IN6 (solid shape): 306.21,48.01 306.21,47.37 306.08,47.24 303.86,47.24 303.79,47.31 303.79,48.07 303.92,48.2 306.02,48.2
N32295402 on TOP (solid shape): 309.52,51.95 309.52,50.73 310.05,50.2 310.05,49.51 309.84,49.29 308.17,49.29 308.09,49.37 308.09,49.98 308.61,50.5 308.61,51.65 308.48,51.78 308,51.78 307.88,51.89 307.88,52.45 307.97,52.53 308.94,52.53
N32295402 on BOTTOM (solid shape): 289.39,39.48 289.39,38.41 289.28,38.3 288.01,38.3 287.91,38.39 287.91,39.55 287.99,39.63 289.23,39.63
N32295402 on BOTTOM (solid shape): 289.46,45.18 289.46,44.04 289.16,43.75 288.81,43.75 288.3,44.26 288.3,45.12 288.54,45.37 289.27,45.37
N32295402 on IN1 (solid shape): 290.3,44.7 290.3,43.81 290.14,43.66 288.56,43.66 288.31,43.9 288.31,44.65 288.42,44.76 290.24,44.76
N32295402 on IN1 (solid shape): 309.35,51.12 309.35,49.2 309.28,49.12 308.41,49.12 308.34,49.19 308.34,51.14 308.47,51.27 309.2,51.27
N32295402 on IN2 (solid shape): 289.44,44.39 289.44,42.71 289.32,42.58 288.51,42.58 288.43,42.67 288.43,43.33 288.31,43.45 288.31,44.6 288.48,44.77 289.06,44.77
N32295402 on IN2 (solid shape): 289.44,40.2 289.44,38.75 288.76,38.07 288.16,38.07 287.89,38.34 287.89,38.87 288.43,39.41 288.43,40.18 288.52,40.28 289.36,40.28
N32424441 on BOTTOM (solid shape): 244.68,41.07 246.4,41.07 246.81,40.66 246.81,39.48 246.79,39.45 246.25,39.45 246.19,39.51 243.31,39.51 243.19,39.64 243.19,39.78 242.89,40.08 242.89,41.6 242.95,41.66 244.09,41.66
N32424758 on BOTTOM (solid shape): 241.38,43.6 241.38,43.13 241.5,43.01 241.5,42.19 241.45,42.14 240.84,42.14 240.77,42.21 240.77,43.61 240.87,43.71 241.27,43.71
N32424883 on BOTTOM (solid shape): 249.05,43.35 249.05,41.31 248.98,41.25 248.3,41.25 248.24,41.31 248.24,43.37 248.28,43.41 248.98,43.41
N32424887 on BOTTOM (solid shape): 246.78,42.29 247.49,42.29 247.63,42.14 247.63,41.28 247.55,41.2 244.74,41.2 244.16,41.79 243.02,41.79 242.92,41.89 242.92,42.02 243.24,42.34 246.73,42.34
N32425629 on BOTTOM (solid shape): 122.91,114.93 122.91,113.17 122.83,113.09 122.41,113.09 122.24,113.26 122.24,114.03 121.92,114.35 121.92,115.15 121.99,115.22 122.62,115.22
N32426131 on BOTTOM (solid shape): 119.85,113.58 119.85,112.72 119.71,112.58 118.11,112.58 117.85,112.83 117.85,113.7 117.93,113.78 119.65,113.78
N32856423 on TOP (solid shape): 228.1,152.89 228.1,152.3 228.1,152.29 228.2,152.2 228.2,151.99 228.06,151.86 227.88,151.86 227.72,152.01 227.73,152.13 227.72,152.21 227.72,152.36 227.61,152.47 227.46,152.47 227.39,152.48 227.31,152.48 227.28,152.51 227.28,152.99 227.3,153.01 227.98,153.01
N32856423 on BOTTOM (solid shape): 228.19,152.22 228.19,151.95 227.88,151.64 227.88,150.88 227.78,150.78 227.62,150.78 227.55,150.86 227.55,151.69 227.74,151.88 227.74,152.05 227.73,152.08 227.74,152.16 227.76,152.2 227.77,152.23 227.77,152.24 227.88,152.36 228.06,152.36
N32856454 on TOP (solid shape): 229.12,153.07 229.12,152.43 229.12,152.43 229.12,152.04 228.9,151.83 228.49,151.83 228.32,151.99 228.32,152.31 228.23,152.41 228.23,152.95 228.23,153.07 228.24,153.08 229.12,153.08
N32856474 on TOP (solid shape): 229.18,154.4 229.18,153.83 228.7,153.35 227.31,153.35 227.28,153.38 227.28,153.96 227.34,154.02 227.78,154.02 228.29,154.53 229.05,154.53
N32868428 on BOTTOM (solid shape): 214.31,153.16 214.31,152.16 214.34,152.14 214.34,151.71 214.3,151.63 214.28,151.54 214.28,150.96 214.29,150.89 214.18,150.78 213.96,150.78 213.89,150.86 213.89,151.87 214,152 214,152.25 213.76,152.5 213.66,152.5 213.51,152.65 213.51,153.2 213.53,153.22 214.25,153.22
N32868434 on BOTTOM (solid shape): 215.25,153.04 215.29,153.03 215.34,153.03 215.34,152.4 215.34,152.4 215.34,151.79 215.27,151.72 215.27,151.6 215.23,151.55 215.23,150.89 215.13,150.79 214.97,150.79 214.89,150.88 214.89,151.76 214.44,152.21 214.44,153.04 214.46,153.06 215.2,153.06
N32868438 on BOTTOM (solid shape): 215.4,154.4 215.4,153.83 215.31,153.74 215.24,153.73 215.17,153.7 214.45,153.7 214.26,153.51 213.56,153.51 213.5,153.58 213.5,154.15 213.88,154.53 215.27,154.53
N32872467 on TOP (solid shape): 242.83,153.17 242.83,152.26 242.44,151.86 241.95,151.86 241.78,152.03 241.79,152.11 241.78,152.16 241.78,153.22 241.81,153.25 242.76,153.25
N32872467 on BOTTOM (solid shape): 242.61,152.14 242.61,150.96 242.51,150.87 242.35,150.87 242.27,150.95 242.27,151.67 242.06,151.88 241.93,151.89 241.79,152.03 241.79,152.25 241.91,152.37 242.37,152.37
N32872469 on TOP (solid shape): 242.83,154.56 242.83,153.99 242.32,153.48 240.99,153.48 240.93,153.54 240.93,154.11 240.99,154.18 241.44,154.18 241.94,154.69 242.71,154.69
N32872885 on TOP (solid shape): 256.61,153.19 256.61,152.56 256.61,152.56 256.61,152.22 256.34,151.95 255.72,151.95 255.58,152.09 255.58,152.41 255.72,152.55 255.72,153.18 255.74,153.2 256.61,153.2
N32872885 on BOTTOM (solid shape): 256.37,152.22 256.37,151.02 256.27,150.92 256.14,150.92 256.06,151 256.06,151.79 255.91,151.94 255.76,151.94 255.71,151.95 255.58,152.08 255.58,152.31 255.69,152.42 256.17,152.42
N72585933 on TOP (solid shape): 98.5,36.1 98.5,34.64 97.74,33.88 97.1,33.88 96.97,34 96.97,34.77 96.66,35.08 96.66,36.1 96.78,36.23 98.37,36.23

Small or netless copper shapes (teardrops, artwork), in the pictures only: 157 on TOP, 241 on BOTTOM, 1 on IN1, 1 on IN4

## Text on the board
Ref Des/Silkscreen Bottom: SPEAKER | HDD/SSD | C17 | FOR | only support for DDR4&JDIMM1/JDIMM2 | TRON LIGHT L | TRON LIGHT R | DC IN | BATTERY | JDIMM1 | JDIMM2 | MK | KB BL | TP | KB | RTC | SSD-2 | MK BL | ONLY FOR DDR4 | WLAN
User.Comments: LA-D751P | 2016-08-15 | 2017-08-15 | BAP10 | Win
Ref Des/Silkscreen Top: CPU FAN | GPU FAN | TOBII | EDP | LOGO | POWER | USB BOARD
GND4: GND4
IN5: IN5
GND5: GND5
IN6: IN6
GND6: GND6
BODY_CENTER: LAYER | NAME | L3 | L1 | L2 | L5 | L4 | L6 | L7 | L8 | L9 | L10 | L11 | L14 | L12 | L13 | LA-D751P | GND5 | GND2 | GND6 | GND3 | GND4 | TOP | GND1 | IN2 | IN4 | IN3 | IN1 | IN5 | IN6 | BOT | LS-XXXXP
User.43: 4.3 / 3.5
User.44: FIGURE | SIZE | 8.0 | 20.0 | 22.0 | 30.0 | 35.0 | 36.0 | 39.0 | 90.0 | 118.0 | 142.0 | 150.0 | 26.0 | 43.0 | 47.0 | 63.0 | 49.0x28.0 | 55.0x24.0 | 63.0x35.0 | 67.0x24.0 | 69.0x28.0 | 75.0x24.0 | 75.0x28.0 | 79.0x31.0 | 94.0x24.0 | 94.0x28.0 | 161.0x142.0 | 165.0x142.0 | 33.0x26.0 | DRILL CHART: TOP to BOTTOM | ALL UNITS ARE IN MILS | TOLERANCE | +3.0/-3.0 | +2.0/-2.0 | PLATED | NON-PLATED | QTY | 11714 | 10 | 19 | 1 | 8 | 9 | 5 | 14 | 2 | 6 | 4
